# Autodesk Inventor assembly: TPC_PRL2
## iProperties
Shininess: 64.0
Length Units: 11272
Angle Units: 11279
Time Units: 11290
Mass Units: 11286
Length Display Precision: 3
Angle Display Precision: 2
Compacted: True
Part Number: TPC_PRL2
Document SubType Name: Assembly
Created: 2004-08
Designer: Lori
Manufacturer: Standard
Standards Organization: Custom
Density: 0.0
Volumn: 0.0
Area: 0.0
PropertySet Name: Model Information
Control State: 0
Master: False
Checked Out: False
Author: Lori
